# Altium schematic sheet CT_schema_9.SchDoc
size 281 x 153 mm
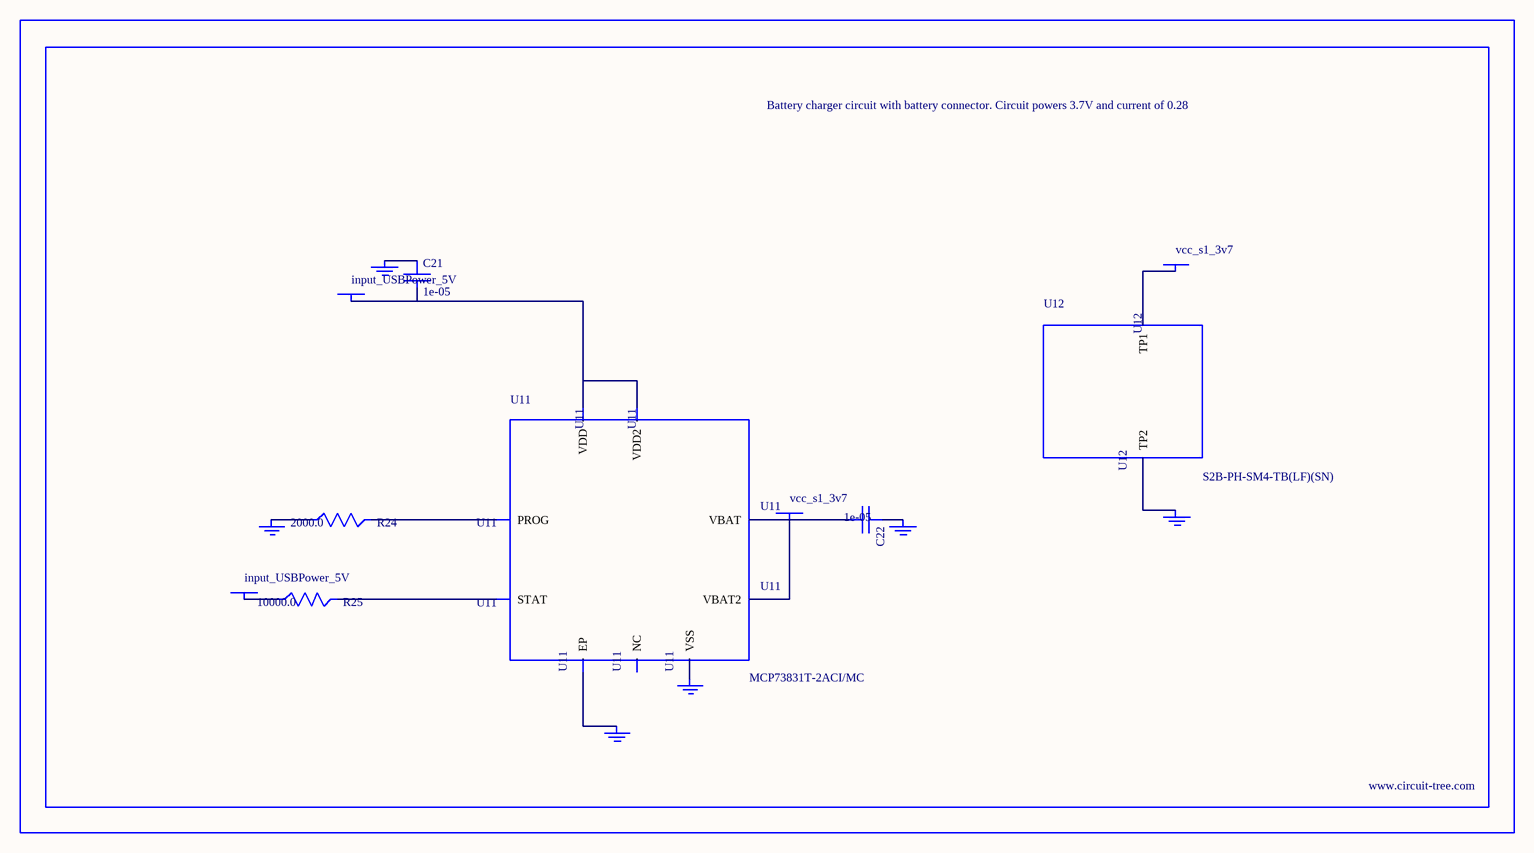
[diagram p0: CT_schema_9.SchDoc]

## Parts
BORDER8  (no value)
C21  1e-05  [C1206]
C22  1e-05  [C1206]
GND_INSTANCE_8_0  (no value)
GND_INSTANCE_8_1  (no value)
GND_INSTANCE_8_2  (no value)
GND_INSTANCE_8_3  (no value)
GND_INSTANCE_8_4  (no value)
GND_INSTANCE_8_5  (no value)
POWER_INSTANCE_8_0  input_USBPower_5V
POWER_INSTANCE_8_1  input_USBPower_5V
POWER_INSTANCE_8_2  vcc_s1_3v7
POWER_INSTANCE_8_3  vcc_s1_3v7
R24  2000.0  [R0603]
R25  10000.0  [R0603]
U11  MCP73831T-2ACI/MC  [DFN8_2X3MC]
U12  S2B-PH-SM4-TB(LF)(SN)  [JST-2-SMD]

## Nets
NetC21_1: C21.1 GND_INSTANCE_8_0.0(GND)
NetC21_2: C21.2 POWER_INSTANCE_8_0.0(PWR) U11.1(VDD) U11.2(VDD2)
NetC22_1: C22.1 GND_INSTANCE_8_1.0(GND)
NetC22_2: C22.2 POWER_INSTANCE_8_2.0(PWR) U11.3(VBAT) U11.4(VBAT2)
NetGND_INSTANCE_8_2_0: GND_INSTANCE_8_2.0(GND) R24.1
NetGND_INSTANCE_8_3_0: GND_INSTANCE_8_3.0(GND) U11.9(EP)
NetGND_INSTANCE_8_4_0: GND_INSTANCE_8_4.0(GND) U11.6(VSS)
NetGND_INSTANCE_8_5_0: GND_INSTANCE_8_5.0(GND) U12.2(TP2)
NetPOWER_INSTANCE_8_1_0: POWER_INSTANCE_8_1.0(PWR) R25.1
NetPOWER_INSTANCE_8_3_0: POWER_INSTANCE_8_3.0(PWR) U12.1(TP1)
NetR24_2: R24.2 U11.8(PROG)
NetR25_2: R25.2 U11.5(STAT)

Not connected (* = marked no-connect by the designer): U11 7(NC)

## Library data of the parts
BORDER8 = BORDER_PAGE8
C21 C22 = C1206C106K3RACTU
GND_INSTANCE_8_0-GND_INSTANCE_8_5 = GND
POWER_INSTANCE_8_0-POWER_INSTANCE_8_3 = PWR
R24 = RC0603JR-072KL
R25 = RC0603JR-0710KL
